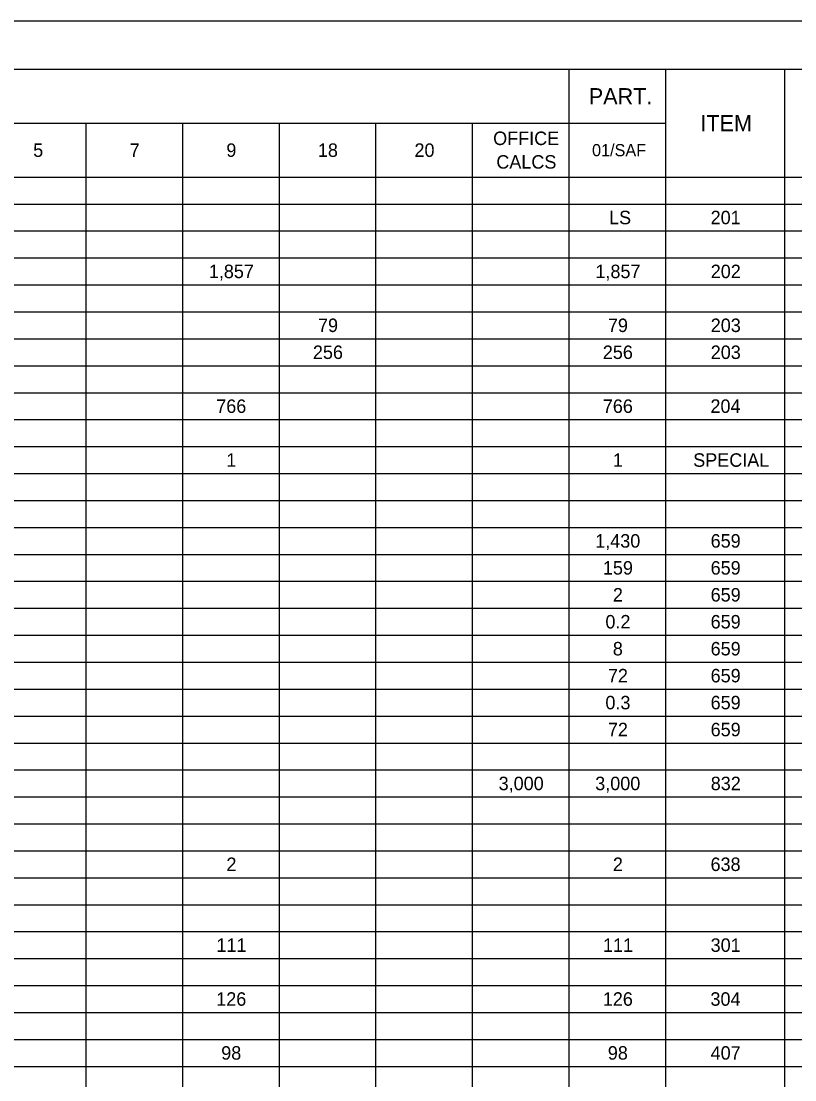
# Model space of a CAD drawing. Extents: x 0 to 34, y 0 to 22.
# Drawn here: x 8.87 to 16.91, y 11 to 22 of the extents above; entities that cross this region are included whole.
import ezdxf

# ---------------------------------------------------------------- set-up
doc = ezdxf.new("R2010")
doc.units = 0
for name, color, linetype in [('Default', 7, 'Continuous'), ('SH_Border', 7, 'Continuous'), ('SH_Cut_Line', 7, 'Continuous')]:
    doc.layers.add(name, color=color, linetype=linetype)

msp = doc.modelspace()

# ---------------------------------------------------------------- linework, layer by layer
at = {"layer": 'Default'}
for p, q in [((1.5, 21.5), (32.002, 21.5)), ((14.561, 21.5), (14.561, 0.501)), ((15.565, 21.5), (15.565, 0.501)), ((16.801, 21.5), (16.801, 0.501)), ((1.5, 20.94), (15.565, 20.94)), ((9.537, 20.94), (9.537, 0.501)), ((10.542, 20.94), (10.542, 0.501)), ((11.547, 20.94), (11.547, 0.501)), ((12.551, 20.94), (12.551, 0.501)), ((13.556, 20.94), (13.556, 0.501)), ((1.5, 20.38), (32.002, 20.38)), ((1.5, 20.1), (32.002, 20.1)), ((1.5, 19.82), (32.002, 19.82)), ((1.5, 19.54), (32.002, 19.54)), ((1.5, 19.26), (32.002, 19.26)), ((1.5, 18.98), (32.002, 18.98)), ((1.5, 18.7), (32.002, 18.7)), ((1.5, 18.42), (32.002, 18.42)), ((1.5, 18.14), (32.002, 18.14)), ((1.5, 17.86), (32.002, 17.86)), ((1.5, 17.58), (32.002, 17.58)), ((1.5, 17.3), (32.002, 17.3)), ((1.5, 17.02), (32.002, 17.02)), ((1.5, 16.74), (32.002, 16.74)), ((1.5, 16.46), (32.002, 16.46)), ((1.5, 16.18), (32.002, 16.18)), ((1.5, 15.9), (32.002, 15.9)), ((1.5, 15.62), (32.002, 15.62)), ((1.5, 15.34), (32.002, 15.34)), ((1.5, 15.06), (32.002, 15.06)), ((1.5, 14.78), (32.002, 14.78)), ((1.5, 14.5), (32.002, 14.5)), ((1.5, 14.22), (32.002, 14.22)), ((1.5, 13.94), (32.002, 13.94)), ((1.5, 13.66), (32.002, 13.66)), ((1.5, 13.38), (32.002, 13.38)), ((1.5, 13.1), (32.002, 13.1)), ((1.5, 12.82), (32.002, 12.82)), ((1.5, 12.54), (32.002, 12.54)), ((1.5, 12.26), (32.002, 12.26)), ((1.5, 11.98), (32.002, 11.98)), ((1.5, 11.7), (32.002, 11.7)), ((1.5, 11.42), (32.002, 11.42)), ((1.5, 11.14), (32.002, 11.14))]:
    msp.add_line(p, q, dxfattribs=at)
at = {"layer": 'SH_Border'}
msp.add_lwpolyline([(1.5, 21.5), (33.5, 21.5), (33.5, 0.5), (1.5, 0.5)], close=True, dxfattribs=at)
at = {"layer": 'SH_Cut_Line'}
msp.add_lwpolyline([(0, 0), (34, 0), (34, 22), (0, 22)], close=True, dxfattribs=at)

# ---------------------------------------------------------------- texts
at = {"layer": 'Default'}
for s, height, p in [('PART.', 0.168, (14.767, 21.136)), ('ITEM', 0.168, (15.927, 20.856)), ('OFFICE ', 0.14, (13.773, 20.713)), ('5', 0.14, (8.991, 20.59)), ('7', 0.14, (9.994, 20.59)), ('9', 0.14, (10.999, 20.59)), ('18', 0.14, (11.951, 20.59)), ('20', 0.14, (12.955, 20.59)), ('01/SAF', 0.126, (14.801, 20.597)), ('CALCS', 0.14, (13.806, 20.468)), ('LS', 0.14, (14.978, 19.89)), ('201', 0.14, (16.034, 19.89)), ('1,857', 0.14, (10.817, 19.33)), ('1,857', 0.14, (14.836, 19.33)), ('202', 0.14, (16.035, 19.33)), ('79', 0.14, (11.952, 18.77)), ('79', 0.14, (14.966, 18.77)), ('203', 0.14, (16.035, 18.77)), ('256', 0.14, (11.899, 18.49)), ('256', 0.14, (14.913, 18.49)), ('203', 0.14, (16.035, 18.49)), ('766', 0.14, (10.894, 17.93)), ('766', 0.14, (14.913, 17.93)), ('204', 0.14, (16.032, 17.93)), ('1', 0.14, (10.999, 17.37)), ('1', 0.14, (15.018, 17.37)), ('SPECIAL', 0.14, (15.853, 17.37)), ('1,430', 0.14, (14.834, 16.53)), ('659', 0.14, (16.034, 16.53)), ('159', 0.14, (14.914, 16.25)), ('659', 0.14, (16.034, 16.25)), ('2', 0.14, (15.018, 15.97)), ('659', 0.14, (16.034, 15.97)), ('0.2', 0.14, (14.94, 15.69)), ('659', 0.14, (16.034, 15.69)), ('8', 0.14, (15.017, 15.41)), ('659', 0.14, (16.034, 15.41)), ('72', 0.14, (14.966, 15.13)), ('659', 0.14, (16.034, 15.13)), ('0.3', 0.14, (14.94, 14.85)), ('659', 0.14, (16.034, 14.85)), ('72', 0.14, (14.966, 14.57)), ('659', 0.14, (16.034, 14.57)), ('3,000', 0.14, (13.83, 14.01)), ('3,000', 0.14, (14.834, 14.01)), ('832', 0.14, (16.035, 14.01)), ('2', 0.14, (11, 13.17)), ('2', 0.14, (15.018, 13.17)), ('638', 0.14, (16.033, 13.17)), ('111', 0.14, (10.896, 12.33)), ('111', 0.14, (14.915, 12.33)), ('301', 0.14, (16.034, 12.33)), ('126', 0.14, (10.894, 11.77)), ('126', 0.14, (14.913, 11.77)), ('304', 0.14, (16.032, 11.77)), ('98', 0.14, (10.946, 11.21)), ('98', 0.14, (14.965, 11.21)), ('407', 0.14, (16.034, 11.21))]:
    msp.add_text(s, height=height, dxfattribs=at).set_placement(p)

doc.saveas('drawing.dxf')
